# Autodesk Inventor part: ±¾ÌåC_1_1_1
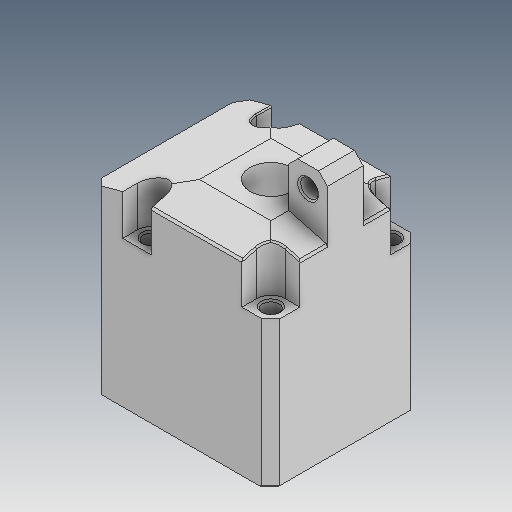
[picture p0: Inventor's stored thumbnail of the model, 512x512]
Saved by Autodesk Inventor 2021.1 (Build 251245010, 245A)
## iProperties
Created: 2019-04
Part Number: ±¾ÌåC_1_1_1
Material: Ogólny
Document SubType Name: Modeling
Designer: user
Density: 1 g/cm^3
Appearance: Domyślna
Author: user
Revision Number: ÈÎºÎ
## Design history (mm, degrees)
feature "ÊäÈë1"
feature "ÊäÈë2"
node "Bryła1"
node "Bryła2"
